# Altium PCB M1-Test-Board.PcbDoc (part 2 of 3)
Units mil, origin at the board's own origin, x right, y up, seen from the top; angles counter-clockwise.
Board outline 3977 x 5000 mil, 4 copper layers (Top, GND Layer 2, Power Layer 3, Bottom), stack 60 mil thick; 191 components, 124 nets, 579 pads, 189 vias.
Unrouted connection lines stored in the file: 80.
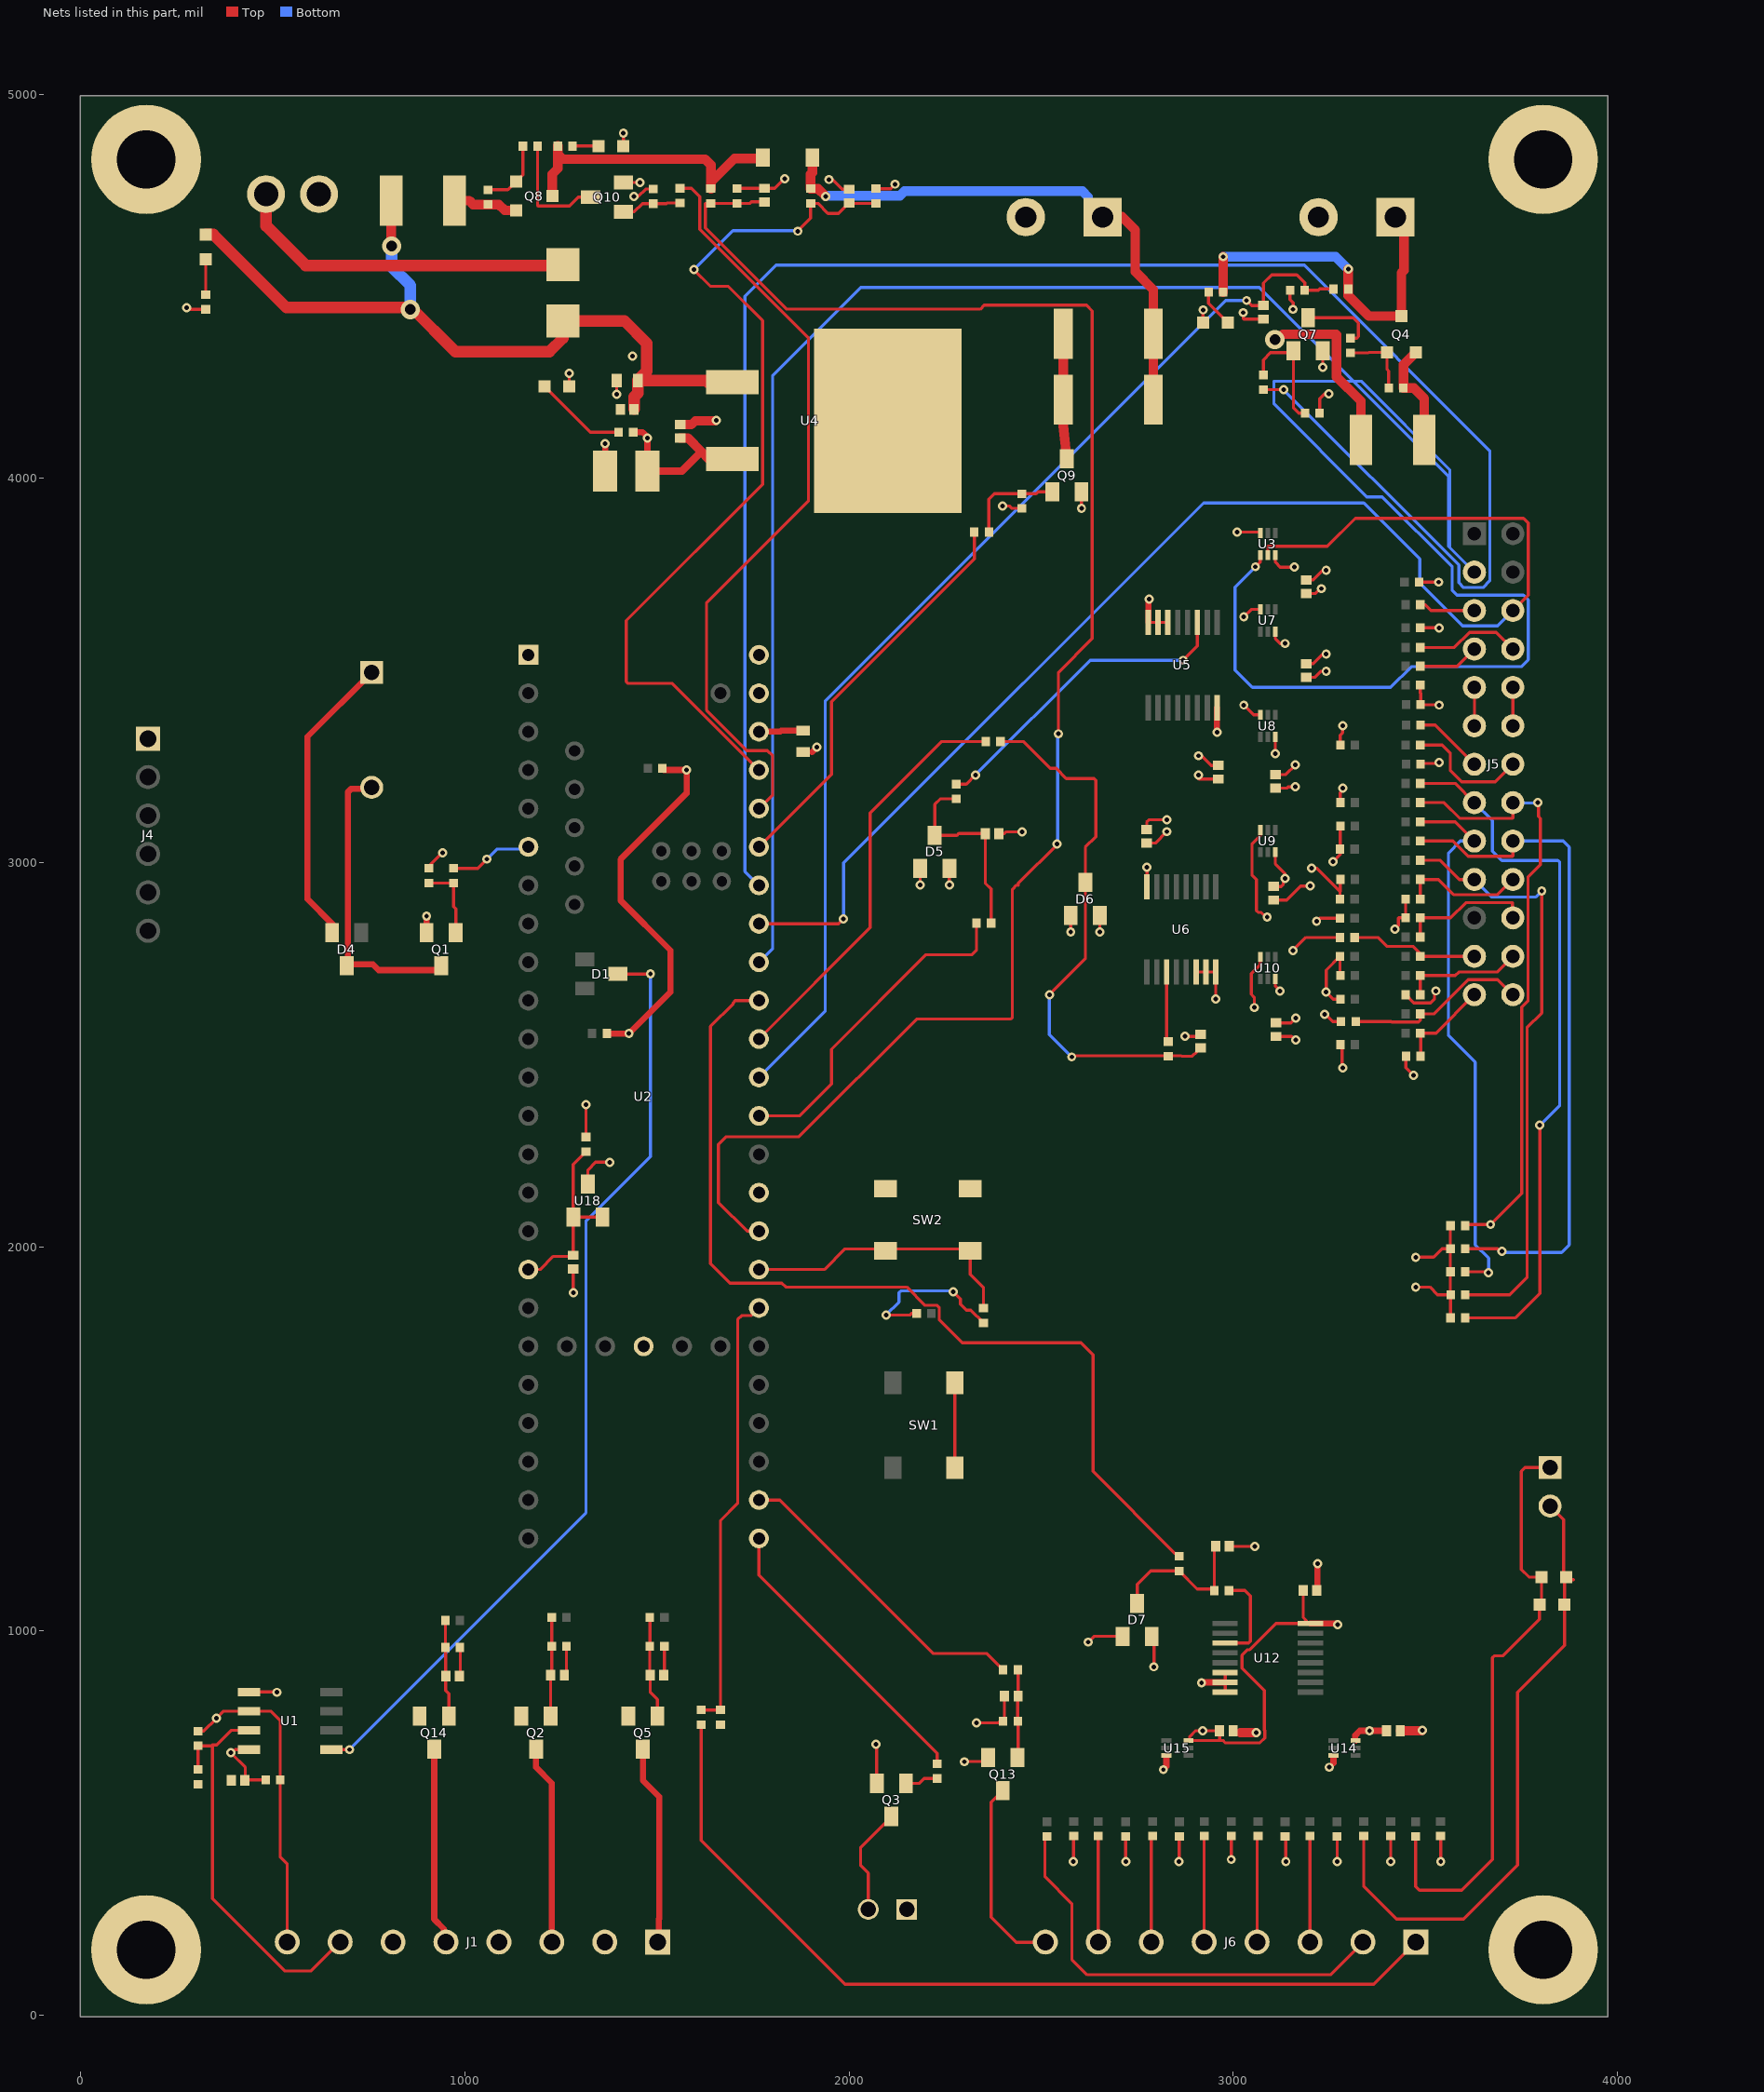
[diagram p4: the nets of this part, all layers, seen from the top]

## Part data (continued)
R2 R3 R8 R22 R23 R24 R25 R26 R27 R28 R29 R30 R31 R32 R33 R34 R35 R36 R37 R38 R39 R40 R41 R42 R43 R44 R45 R46 R47 R48 R49 R52 R60 R61 R62 R63 R64 R65 R66 R67 R70 R73 R88 R90 R92 R94 R99 R100 R102 R103 R104 R108 R117 R118 R119 R120 R121: library part Res-00002, "Thick Film 0402 10K OHM 1% 1/16W 0402", Case Code (Imperial)=0402, Case Code (Metric)=1005, LCSC Part Number=C25744, Manufacturer=Yageo, Manufacturer Part Number=RC0402FR-0710KP, Max Operating Temperature=155°C, Max Power Dissipation=63mW, Min Operating Temperature=-55°C, Power Rating=62.5mW, Resistance=10k, Resistor Type="Thick Film", Supplier Part Number 1=YAG1249CT-ND, Temperature Coefficient=150ppm/°C, Tolerance=1%
R4 R5 R82: library part Res-00009, "Thick Film 0402 330 Ohm 1% 1/16W ±100ppm/°C Molded SMD Paper T/R", Case Code (Imperial)=0402, Case Code (Metric)=1005, LCSC Part Number=C12246, Manufacturer=Yageo, Manufacturer Part Number=AF0402FR-07330RL, Max Operating Temperature=155°C, Max Power Dissipation=63mW, Min Operating Temperature=-55°C, Power Rating=62.5mW, Resistance=330R, Resistor Type="Thick Film", Supplier Part Number 1=13-AF0402FR-07330RLCT-ND, Temperature Coefficient=100ppm/°C, Tolerance=1%
R6 R89 R101 R113: library part Res-00004, "Thick Film 0402 5.1K Ohm 1% 1/16W 0402", Case Code (Imperial)=0402, Case Code (Metric)=1005, LCSC Part Number=C25905, Manufacturer="Stackpole Electronics", Manufacturer Part Number=RMCF0402FT5K10, Max Operating Temperature=155°C, Max Power Dissipation=63mW, Min Operating Temperature=-55°C, Power Rating=62.5mW, Resistance=5.1k, Resistor Type="Thick Film", Supplier Part Number 1=RMCF0402FT5K10CT-ND, Temperature Coefficient=100ppm/°C, Tolerance=1%
R7 R85: library part Res-00001, "Thick Film 0402 1K Ohm 1% 1/8W 0402", Case Code (Imperial)=0402, Case Code (Metric)=1005, LCSC Part Number=C21190, Manufacturer="TE Connectivity", Manufacturer Part Number=CRGP0402F1K0, Max Operating Temperature=155°C, Max Power Dissipation=125mW, Min Operating Temperature=-55°C, Power Rating=0.125W, Resistance=1k, Resistor Type="Thick Film", Supplier Part Number 1=A130355CT-ND, Temperature Coefficient=100ppm/°C, Tolerance=1%
R9 R10 R96 R105 R109 R116 R124 R125: library part Res-00003, "Thick Film 0402 100K OHM 1% 1/16W 0402", Case Code (Imperial)=0402, Case Code (Metric)=1005, LCSC Part Number=C25741, Manufacturer="Stackpole Electronics", Manufacturer Part Number=RMCF0402FT100K, Power Rating=62.5mW, Supplier Part Number 1=RMCF0402FT100KCT-ND
R11 R12 R13 R14 R15 R16 R50 R51 R53 R54 R55 R56 R57 R68 R69 R71 R72: library part Res-00011, "Res Thick Film 0402 51K Ohm 1% 0.063W(1/16W) ±100ppm/C Pad SMD Automotive T/R", Case Code (Imperial)=0402, Case Code (Metric)=1005, LCSC Part Number=C25794, Manufacturer="Stackpole Electronics", Manufacturer Part Number=RMCF0402FT51K0, Max Operating Temperature=155°C, Max Power Dissipation=63mW, Min Operating Temperature=-55°C, Resistance=51kR, Resistor Type="Thick Film", Supplier Part Number 1=RMCF0402FT51K0CT-ND, Temperature Coefficient=100ppm/°C, Tolerance=1%
R17 R21 R58 R59 R93 R106 R107 R111 R112 R114: library part Res-00008, "Thick Film 0402 2.8K Ohm 1% 0.063W ±100ppm/°C Molded SMD Paper T/R", Case Code (Imperial)=0402, Case Code (Metric)=1005, LCSC Part Number=C62741, Manufacturer="Stackpole Electronics", Manufacturer Part Number=RMCF0402FT2K80, Max Operating Temperature=155°C, Max Power Dissipation=63mW, Min Operating Temperature=-55°C, Power Rating=62.5mW, Resistance=2.8kR, Resistor Type="Thick Film", Supplier Part Number 1=RMCF0402FT2K80CT-ND, Temperature Coefficient=100ppm/°C, Tolerance=1%
R18 R19 R20: library part Res-00012, "Res Thick Film 0402 8.2K Ohm 5% 0.063W ±100ppm/°C Molded SMD Paper T/R", Case Code (Imperial)=0402, Case Code (Metric)=1005, LCSC Part Number=C25924, Manufacturer="Stackpole Electronics", Manufacturer Part Number=RMCF0402JT8K20, Max Operating Temperature=155°C, Max Power Dissipation=63mW, Min Operating Temperature=-55°C, Resistance=8.2kR, Resistor Type="Thick Film", Supplier Part Number 1=738-RMCF0402JT8K20CT-ND, Temperature Coefficient=100ppm/°C, Tolerance=5%
R97 R98: library part Res-00005, "Thick Film  220 OHM 5% 1W 2512", Case Code (Imperial)=2512, Case Code (Metric)=6432, LCSC Part Number=C38808, Manufacturer="Stackpole Electronics", Manufacturer Part Number=RMCF2512JT220R, Max Operating Temperature=155°C, Max Power Dissipation=1W, Min Operating Temperature=-55°C, Resistance=220R, Resistor Type="Thick Film", Supplier Part Number 1=RMCF2512JT220RCT-ND, Temperature Coefficient=200ppm/°C, Tolerance=5%
R110: library part Res-00010, "Thick Film 0402 680 Ohm 1% 0.063W(1/16W) ±100ppm/C Pad SMD Automotive T/R", Case Code (Imperial)=0402, Case Code (Metric)=1005, LCSC Part Number=C25130, Manufacturer="Stackpole Electronics", Manufacturer Part Number=RMCF0402FT680R, Max Operating Temperature=155°C, Max Power Dissipation=63mW, Min Operating Temperature=-55°C, Package Quantity=10000, Power Rating=62.5mW, Resistance=680R, Resistor Type="Thick Film", Supplier Part Number 1=RMCF0402FT680RCT-ND, Temperature Coefficient=100ppm/°C, Tolerance=1%
SW1: library part SW-0002, "Switch Tactile N.O. SPST Round Button J-Bend", Case/Package=SMD/SMT, Color=Black, Contact Current Rating=50mA, LCSC Part Number=C221748, Manufacturer="ITT C&K", Max Operating Temperature=85°C, Max Voltage Rating (DC)=32V, Min Operating Temperature=-40°C, Operating Force=5N, Package Quantity=1, Power Rating=1W, Supplier Part Number 1=401-1784-1-ND
SW2: library part SW-0001, "Switch Tactile N.O. SPST Round Button J-Bend", Actuator Color=Blue, Case/Package=SMD/SMT, Current Rating=50mA, LCSC Part Number=C221766, Manufacturer="ITT C&K", Manufacturer Part Number=KSC741JLFS, Max Operating Temperature=85°C, Max Voltage Rating (DC)=32V, Min Operating Temperature=-40°C, Operating Force=4N, Package Quantity=1000, Power Rating=1W, Ratings="IP67,Waterproof,Dust Tight", Supplier Part Number 1=CKN10309CT-ND
U1: library part dd-0001, "IC TXRX RS485 HALF DUPLEX 8SOIC", BOM_JLCPCB Part Class="Basic Part", BOM_Manufacturer=EXAR, BOM_Manufacturer Part=SP485EEN-L/TR, Case/Package=SOIC, LCSC Part Number=C6855, Manufacturer=Exar, Max Operating Temperature=85°C, Max Power Dissipation=550mW, Max Supply Voltage=5.25V, Min Operating Temperature=-40°C, Min Supply Voltage=4.75V, Nominal Supply Current=900uA, Operating Supply Voltage=5V, Package Display=No, Package Quantity=2500
U2: library part Mod-0004, "Teensy 4.1 Development Board", Manufacturer=SparkFun, Manufacturer Part Number=DEV-16771, Supplier Part Number 1=1568-DEV-16771-ND
U3 U7 U8 U9 U10 U14 U15: library part Diode-0012, "TVS DIODE 5.5VWM SOT6", Breakdown Voltage=11V, Capacitance=1.5pF, Case/Package=SOT, Clamping Voltage=105.5V, LCSC Part Number=C527516, Leakage Current=1nA, Manufacturer="Texas Instruments", Max Operating Temperature=85°C, Max Power Dissipation=100W, Min Operating Temperature=-40°C, Operating Supply Voltage=5.5V, Package Quantity=1, Peak Pulse Current=5.5A, Power Line Protection=Yes, Supplier Part Number 1=296-21887-1-ND
U4: library part LDO-0003, "IC REG LDO 5V 1.5A D2PAK", Case/Package=TO-263, Dropout Voltage=2V, LCSC Part Number=C15077, Manufacturer=STMicroelectronics, Max Input Voltage=35V, Max Operating Temperature=125°C, Max Output Current=1.5A, Min Input Voltage=10V, Min Operating Temperature=0°C, Min Output Voltage=4.8V, Nominal Output Voltage=5V, Package Quantity=1000, Power Supply Rejection Ratio (PSRR)=62dB, Quiescent Current=8mA, Supplier Part Number 1=497-1171-2-ND
U5 U6 U12: library part AIC-0001, "5-V, 8: 1, 1-channel analog mutliplexer 16-TS", Case/Package=TSSOP, Dual Supply Voltage=3V, Generic Part Number=CD74HC4051, High Level Output Current=25mA, LCSC Part Number=C352826, Manufacturer="Texas Instruments", Max Dual Supply Voltage=5V, Max Operating Temperature=125°C, Max Supply Voltage=6V, Min Dual Supply Voltage=1V, Min Operating Temperature=-55°C, Min Supply Voltage=2V, Nominal Supply Current=16uA, On-State Resistance=130R, Operating Temperature Range(C)="-55 to 125", Package Quantity=1, Rating=Catalog, Supplier Part Number 1=29AH3620
U18: library part AIC-0002, "V-Ref Adjustable 2.5V to 36V 100mA 3-Pin SOT-", Case/Package=SOT-23-3, Cathode Current=60uA, LCSC Part Number=C3113, Manufacturer="ON Semiconductor", Max Input Voltage=2.525V, Max Operating Temperature=125°C, Max Output Current=100mA, Max Output Voltage=36V, Min Input Voltage=2.475V, Min Operating Temperature=-40°C, Min Output Voltage=2.5V, Package Quantity=3000, PartNumber=TL431ACLP, Rating=Catalog, Supplier Part Number 1=NCP431AVSNT1GOSCT-ND, Temp Coeff(Max)(ppm/ degree C)=92, Temp Coeff(Typ)(ppm/ degree C)=34, Temperature Coefficient=50ppm/°C, Tolerance=1%

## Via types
v1: diameter 24, hole 12, Top to Bottom, 186 vias
v2: diameter 50, hole 28, Top to Bottom, 3 vias

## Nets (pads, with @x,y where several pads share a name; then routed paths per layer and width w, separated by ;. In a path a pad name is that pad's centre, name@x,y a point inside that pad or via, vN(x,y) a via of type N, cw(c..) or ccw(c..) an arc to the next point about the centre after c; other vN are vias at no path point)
+3.3V: D5.2 D6.2 D7.2 F3.2 R2.2 R6.2 R73.2 R117.2 | length 1603.9
  Top w8: F3.2@1880,3287.44 1903.22,3287.44 ; v1(2096.4,1822.31) 2159.03,1822.31 2162.88,1826.16 R2.2@2175.91,1826.16 ; v1(2261,2942) D5.2@2261,2985 ; v1(2271.4,1882.31) 2289.98,1863.73 2289.98,1850.52 2305.5,1835 2316.9,1835 R73.2@2350,1801.9 ; v1(2653,2819) D6.2@2653,2862 ; D7.2@2788,985.77 2793.76,980 v1(2793.76,906.57)
  Top w16: R6.2@1369.09,2555 v1(1427,2555) 1535,2663 1535,2771.38 1405,2901.38 1405,3008.19 1577,3180.19 v1(1577,3241) 1518.09,3241 R117.2@1514.09,3245 ; 1903.22,3287.44 v1(1915.72,3299.94)
  Bottom w8: v1(2096.4,1822.31) 2130,1855.92 2130,1880.31 2134.69,1885 2268.71,1885 v1(2271.4,1882.31)
+5V: BUZ1.1 C1.1 C4.2 C6.2 C8.2 C9.2 C10.2 C11.2 C12.2 C15.2 C18.2 C19.2 C27.1 C28.2 D4.2 R4.2 R11.2 R12.2 R13.1 R40.1 R42.2 R43.2 R44.1 R46.1 R48.1 R68.1 R69.1 R82.1 R110.1 U1.8 U2.VIN U3.6 U4.3 U5.16 U6.16 U7.6 U8.6 U9.6 U10.6 U12.16 U14.6 U15.6 | length 4164
  Top w8: v1(390,682.61) v1@391.95,680.65 ; U1.8@437.75,691 402.3,691 v1@391.95,680.65 ; R4.2@480.9,612.21 428.2,612.21 428.2,644.41 v1@391.95,680.65 ; R82.1@1315,2285.47 v1(1315,2370) ; C6.2@2775,3050.6 2797.29,3050.6 v1(2827.19,3080.5) ; U6.16@2775.43,2937 v1(2775.43,2988) ; U15.6@2883.94,714.68 2963.29,714.69 ; 2886.76,720.79 2886.76,725.36 2901.41,740 C19.2@2964.6,740 2964.6,716 2963.29,714.69 ; v1(2909.38,3278) 2917.93,3278 2943.23,3252.7 C8.2@2961.57,3252.7 ; U10.6@3109.69,2696.85 3109.68,2678.36 v1(3122.18,2665.86) ; U9.6@3109.69,3027.06 3109.68,2996.07 3134.68,2971.07 v1(3134.68,2958.57) 3134.68,2954.24 3130,2949.56 3130,2942.39 3125.31,2937.7 C11.2@3105,2937.7 C11.2@3113,2945.7 ; v1(3109.68,3283.57) U8.6@3109.69,3327.06 ; U7.6@3109.69,3601.06 3109.68,3582.57 3122.18,3570.07 v1(3134.68,3570.07) ; U3.6@3109.69,3800 3109.68,3781.51 3122.18,3769.01 v1(3159.68,3769.01) ; C9.2@3110,3229 3136.89,3229 v1(3162.19,3254.3) ; C12.2@3111,2582.7 3150.39,2582.7 v1(3163.19,2595.5) ; v1(3155.5,2771) 3189.5,2805 R43.2@3278,2805 ; C15.2@3182.3,1105 3182.3,1034.55 3190,1026.85 ; C10.2@3190,3517.7 3208.33,3517.7 3233.63,3543 v1(3242.19,3543) ; C4.2@3190,3735.89 3208.33,3735.89 3233.63,3761.19 v1(3242.19,3761.19) ; U12.16@3201,1019.57 3111.57,1019.57 3043,951 3037.5,951 3023,936.5 3023,903 3081,845 3081,742 3082,741 3082,721 3069.5,708.5 2979.19,708.5 2973,714.69 2963.29,714.69 ; v1@3240,2605 3259,2586 R48.1@3280.83,2586 ; v1@3269.06,1019.57 v1@3276.06,1012.57 ; v1(3421,2827) 3430,2836 3430,2855 3431,2856 R44.1@3448.91,2856 R40.1@3448.91,2904.98 ; R46.1@3448.91,2656 3470.22,2634.69 3513.78,2634.69 3524.09,2645 3524.09,2661.09 v1@3528,2665 ; R42.2@3449.81,2496 3449.81,2465.69 v1(3469.5,2446) ; v1(3475,1895) 3512.05,1895 3532.05,1875 R13.1@3566,1875 ; v1(3475,1972.82) 3521.81,1972.82 3544,1995 R11.2@3565.91,1995 ; R13.1@3565,1875 3565,1930 3565,1986.14 R11.2@3565,1989.09 ; R11.2@3565,1990 3565,1995 R12.2@3565,2055 ; R69.1@3565.91,1815 R13.1@3565.91,1874.91
  Top w16: D4.2@655,2840 590,2905 590,3327.73 BUZ1.1@757.27,3495 ; R110.1@1438,4120 1462.5,4120 1473.02,4109.48 1473.02,4109.14 1475,4107.16 v1(1475,4105) 1475,4019.12 C27.1@1475.12,4019 ; v1(2957.95,3339.5) U5.16@2957.95,3403 ; U12.16@3201,1019.57 v1@3269.06,1019.57 ; U14.6@3318.94,714.68 3317.75,715.88 3317.75,728.1 3329.64,740 3339.64,740 C18.2@3399.6,740
  Top w20: C27.1@1475.12,4019 1565,4019 1615.79,4069.79
  Top w24: C28.2@1560,4104.6 1580.97,4104.6 1615.79,4069.79 U4.3@1635.57,4050
  other v1: 2920.94,740.36 3355,740.36 3272.19,1016 3238.37,2604.54 3528,2666
+12V: C25.1 C26.2 D10.2 DS12.1 F1.1 F2.1 U4.1 | length 2498.8
  Top w25: F2.1@807.5,4723.07 808.23,4722.33 808.23,4605.23 v2(808.97,4604.5) ; v2(3108.5,4361.5) 3115.26,4361.5 3128.76,4375 3268,4375 3269,4374 3269,4264.5 3332.5,4201 F1.1@3332.5,4100
  Top w30: DS12.1@325,4634.96 345.04,4634.96 535,4445 860,4445 975,4330 1220,4330 1255,4365 D10.2@1255,4410 1415,4410 1473.02,4351.98 1473.02,4278.54 1450.51,4256.02 C25.1@1450.51,4255 ; C26.2@1440.26,4180 1440.26,4212 1450.51,4222.25 C25.1@1450.51,4255 ; U4.1@1632.57,4250 1627.57,4255 C25.1@1450.51,4255
  Bottom w30: v2(808.97,4604.5) 808.97,4551.03 857.92,4502.08 v2(857.92,4439.5)
BootTarget: R73.1 SW2.3 SW2.4 U2.40 | length 726
  Top w8: U2.40@1765.2,1940.63 1935.63,1940.63 1989.29,1994.29 SW2.3@2305.5,1994.29 ; SW2.3@2315.5,1989.29 2315.5,1928 2350,1893.5 R73.1@2350,1840.09
BuzzerEn: R7.1 U2.4 | length 218.3
  Top w8: R7.1@970,2984.96 1032.96,2984.96 v1(1057,3009)
  Bottom w8: v1(1057,3009) 1083,3035 1159.57,3035 U2.4@1165.2,3040.63
GND: C1.2 C2.2 C3.2 C4.1 C5.2 C6.1 C7.2 C8.1 C9.1 C10.1 C11.1 C12.1 C14.2 C15.1 C18.1 C19.1 C20.2 C22.2 C23.2 C24.2 C25.2 C26.1 C27.2 C28.1 C30.2 C31.2 D5.1 D6.1 D7.1 DS8.2 DS9.2 DS11.2 J1.2 J1.4 J1.6 J4.1 J9.1 J10.2 J11.2 J12.1 MTG1.1 MTG2.1 MTG3.1 MTG4.1 Q1.2 Q2.2 Q3.2 Q5.2 Q7.2 Q9.2 Q10.2 Q13.2 Q14.2 R5.2 R9.2 R10.2 R14.1 R15.1 R16.1 R17.1 R18.1 R19.1 R20.1 R21.1 R38.2 R39.2 R41.1 R45.1 R47.1 R49.1 R50.1 R51.1 R52.1 R53.1 R54.1 R55.1 R56.1 R57.1 R58.1 R59.1 R71.1 R93.2 R96.2 R105.2 R106.2 R107.2 R109.2 R113.2 R116.2 R124.2 R125.2 SW1.1 SW1.2 SW2.1 SW2.2 U1.5 U2.GND1 U2.GND2 U2.GND3 U2.GND4 U3.3 U4.4 U5.6 U5.7 U5.8 U6.6 U6.7 U6.8 U7.3 U8.3 U9.3 U10.3 U12.6 U12.7 U12.8 U14.3 U15.3 U18.3 | length 5592.7
  Top w8: v1(275,4444) 275,4441 276,4440 R113.2@325,4440 ; U1.5@437.75,841 509.09,841 v1(510,840.09) ; R116.2@905.91,2984.96 905.91,2990.91 v1@940,3025 ; C31.2@987.7,882 R125.2@987.7,957 ; C2.2@1258.7,885 1264.09,890.39 R9.2@1264.09,960 ; DS11.2@1271.57,4240 v1(1271.57,4273.75) ; v1(1282,1880) C20.2@1282,1942.3 ; U18.3@1320,2163 1320,2200 1340,2220 v1(1377,2220) ; v1(1395,4219.28) C25.2@1395,4255 ; DS9.2@1412.48,4865 v1(1412.48,4898.75) ; Q10.2@1413,4770.13 v1(1456,4770.13) ; v1(1440,4734.09) 1451.66,4734.09 1470.76,4753.19 R109.2@1490,4753.19 ; C3.2@1517.7,885 1519.09,886.39 R10.2@1519.09,960 ; R106.2@1708,4754.09 1708,4755 C23.2@1780,4755 1806.89,4755 v1(1832.19,4780.3) ; v1(1947.81,4778) 1956.37,4778 1981.67,4752.7 C24.2@2000,4752.7 ; R107.2@2070,4754.09 2108.59,4754.09 2120,4765.5 v1(2120,4765.91) ; Q3.2@2072,603 v1@2072,703.67 ; v1(2185,2942) D5.1@2185,2985 ; SW1.2@2275,1422.42 SW1.1@2275,1643.42 ; v1@2300,660 2352.07,660 Q13.2@2362,669.93 ; v1(2331.97,760.81) 2388.69,760.81 2392.88,765 R124.2@2400.91,765 2404.6,768.69 C30.2@2404.6,830 ; C5.2@2390,3075 2404,3075 2409,3080 v1(2450,3080) ; v1(2400,3928) 2418.11,3928 2424.3,3921.81 R105.2@2450,3921.81 ; v1(2577,2819) D6.1@2577,2862 ; v1(2584.1,400) 2584.1,465 R52.1@2585,465.91 ; v1(2605,3922) Q9.2@2605,3965 ; v1(2622.91,970.81) 2637.87,985.77 D7.1@2712,985.77 ; R53.1@2720,465 2720,400.91 v1(2720.91,400) ; C6.1@2775,3086 2775,3105.38 2780.92,3111.3 v1(2827.19,3111.3) ; U5.8@2779.87,3626.05 U5.8@2778.82,3625 U5.7@2804.41,3625 U5.6@2830,3625 ; v1@2779.87,3684.95 v1(2780.92,3686) ; v1@2819.09,640 v1@2826.06,646.97 ; v1(2859.1,400) 2859.1,464.1 R54.1@2860,465 ; v1(2874.28,2547.56) C7.2@2910,2547.56 ; U6.6@2903.39,2715 U6.7@2928.98,2715 2949.57,2715 2954.57,2710 v1(2954.57,2645) ; v1(2909.38,3227.5) 2909.38,3218.92 2911,3217.3 C8.1@2961.57,3217.3 ; v1(2917.48,865) v1@2918.5,866.02 ; DS8.2@2921.5,4405 v1(2921.5,4438.75) ; U12.8@2979,840.43 U12.7@2979,866.02 U12.6@2979,891.61 ; v1(2995,405) R55.1@2995,465.91 ; C19.1@3000,740 3014,740 3019,735 ; 3002.56,1220 v1@3060,1220 ; v1(3010,3860) 3068.21,3860 U3.3@3070.31,3857.87 ; v1(3026.31,4431.5) 3026.31,4416 3027.71,4414.6 C22.2@3078.5,4414.6 ; v1(3027.71,3410) 3052.78,3384.94 U8.3@3070.31,3384.94 ; v1(3027.71,3640) 3046.65,3658.94 U7.3@3070.31,3658.94 ; v1(3055,2622.5) 3055,2648.95 3047,2656.95 3047,2710.64 3070.31,2733.95 U10.3@3070.31,2754.73 ; U9.3@3070.31,3084.94 3070.31,3069.5 3048.81,3048 3048.81,2967.3 3060.5,2955.62 3060.5,2874.92 3065.19,2870.23 3073.17,2870.23 3084.91,2858.5 v1(3088.39,2858.5) ; C11.1@3105,2902.3 3139.13,2902.3 3175.83,2939 v1(3200.19,2939) ; C9.1@3110,3193.6 3139.28,3193.6 3142.68,3197 v1(3162.19,3197) ; C12.1@3111,2547.3 3152.19,2547.3 3160.99,2538.5 v1(3163.19,2538.5) ; R56.1@3135,465 3136.97,463.03 v1(3136.97,400) ; R93.2@3148.12,4490 3148.12,4465.15 3156,4457.27 v1(3156,4440) ; C10.1@3190,3482.3 3213.13,3482.3 3228.83,3498 v1(3242.19,3498) ; C4.1@3190,3700.49 3214.73,3700.49 3227.24,3713 v1(3229.69,3713) ; v1(3204.5,2985.47) 3217,2985.47 3278.24,2924.24 ; v1@3214.73,2845 3224.73,2855 R47.1@3278,2855 ; R96.2@3225,4170 3225,4207.5 3237.5,4220 v1(3248.91,4220) ; v1(3233,4289) Q7.2@3233,4332 ; v1(3250,645) 3261.06,656.06 ; v1(3260,3002) 3278.91,3020.91 3278.91,3065.91 ; R57.1@3270,465 3270.91,464.09 v1(3270.91,400) ; R50.1@3278,3034.79 3278,3065 3278.91,3065.91 ; R39.2@3278.91,2526 3283.32,2521.59 3283.32,2466.88 v1(3285,2465.19) ; R41.1@3278.91,2644.19 3260.81,2644.19 v1(3242,2663) 3242,2720 R38.2@3278,2756 3278,2706.91 R45.1@3278.91,2706 ; R14.1@3278.91,2956 3278.91,2924.91 3278.24,2924.24 ; R15.1@3278.91,3095 3278.91,3065.91 ; R51.1@3278.91,3156 3278.91,3181.75 3285,3187.84 v1(3285,3193.5) ; R21.1@3278.91,3306 3278.91,3331.75 3285,3337.84 v1(3285,3356) ; v1(3410,400) R58.1@3410,465.91 ; R19.1@3484.09,3730 v1(3535,3730) ; R18.1@3487.09,3462.02 3487.09,3441 3488,3440.09 R17.1@3488,3411 3488.5,3410.5 3535.5,3410.5 v1(3536,3410) ; R20.1@3487.09,3611 v1@3532,3611 ; R16.1@3488,3256 3490,3258 3534,3258 v1(3536,3260) ; v1@3491.5,740 v1(3492.29,740.79) ; R59.1@3540,465.91 3540.41,465.5 v1(3540.41,400) ; 3278.24,2924.24 3278,2924 R49.1@3278,2904.98 3278.24,2924.24
  Top w16: Q1.2@900,2817.42 v1(900,2860.42) ; C27.2@1365.12,4019 v1(1365.12,4090.15) ; U5.8@2779.87,3626.05 v1@2779.87,3684.95 ; v1@2826.06,646.97 U15.3@2826.06,675.32 ; v1@2918.5,866.02 U12.7@2979,866.02 ; C15.1@3217.7,1105 3218.85,1106.15 3218.85,1173.85 v1(3220,1175) ; 3261.06,656.06 U14.3@3261.06,675.32
  Top w24: C28.1@1560,4140 1589.5,4140 1599.5,4150 v1@1652.36,4150 ; 3019,735 v1(3060,735) ; C18.1@3435,740 v1@3491.5,740
  other v1: 2818.19,638.9 2300,659.5 2070,704.48 3055.87,1220.28 3216.93,2847.07 941.93,3025.03 3536,3610.7 1654.31,4151 1436,4318.19
M1Boot1: R70.1 U2.34 | length 818.8
  Top w8: U2.34@1765.2,1340.63 1819.37,1340.63 2218.73,941.27 2358.25,941.27 R70.1@2400.91,898.61
NetBUZ1_2: BUZ1.2 D4.3 Q1.3 | length 787.5
  Top w16: D4.3@692,2731.42 695.58,2735 760,2735 775,2720 928,2720 938,2730 Q1.3@938,2731.42 ; 695,2757.75 695,2740 695,3182.92 704.37,3192.29 753.78,3192.29 BUZ1.2@757.27,3195.79
NetC2_1: C2.1 Q2.1 R3.2 R9.1 | length 258.2
  Top w8: Q2.1@1223,778 1223,884.7 C2.1@1223.3,885 1225.91,887.61 R9.1@1225.91,960 R3.2@1225.91,1035
NetC3_1: C3.1 Q5.1 R8.2 R10.1 | length 265.7
  Top w8: R8.2@1481.91,1035 1481.91,961 R10.1@1480.91,960 1480.91,886.39 C3.1@1482.3,885 1482.3,840.09 1501,821.39 Q5.1@1501,778
NetC5_1: C5.1 D5.3 R111.1 R118.2 | length 505.1
  Top w8: R111.1@2279,3165.91 2237.5,3165.91 2223,3151.41 D5.3@2223,3071 2281,3071 2285.51,3075.51 C5.1@2345,3075.51 ; C5.1@2354.6,3075 2354.6,2946.56 2369.79,2931.36 R118.2@2369.79,2842.52
NetC7_1: C7.1 D6.3 R112.1 R119.2 | length 1428.3
  Top w8: R119.2@2394.09,3315 2453.5,3315 2523.5,3245 2539.3,3245 2565.5,3218.8 2637.56,3218.8 2642.25,3214.11 2642.25,3167.26 ; v1(2521.5,2655.82) 2615,2749.32 D6.3@2615,2948 2615,3040 2642.25,3067.25 2642.25,3165 ; v1@2577.81,2496.81 2830.73,2496.81 2865,2496.81 2865.81,2496 2893.71,2496 2905,2507.29 2905,2509.3 2912.21,2516.51 C7.1@2914.22,2516.51
  Bottom w8: v1(2521.5,2655.82) 2521.5,2552.07 v1(2579.57,2494)
NetC14_1: C14.1 D7.3 R114.1 R120.2 | length 402.1
  Top w8: D7.3@2750,1071.77 2750,1120.8 2785.11,1155.91 R120.2@2859.1,1155.91 2906,1109 2946.91,1109 R114.1@2950.91,1105 2950.91,1216.31 C14.1@2954.6,1220
NetC20_1: C20.1 R82.2 U2.25 U18.1 U18.2 | length 491.4
  Top w8: U2.25@1165.2,1940.63 1195.63,1940.63 1230,1975 1279.3,1975 C20.1@1282,1977.7 U18.1@1282,2077 ; R82.2@1315,2247.28 1282,2214.28 U18.1@1282,2077 ; U18.2@1358,2077 U18.1@1282,2077
NetC22_1: C22.1 R90.1 R93.1 U2.15 | length 2908.7
  Top w8: v1(3035,4463) 3048,4450 C22.1@3078.5,4450 3078.5,4508.5 3100,4530 3165.5,4530 3186.31,4509.19 R93.1@3186.31,4490 3222,4490 3225,4493 R90.1@3261.26,4493
  Bottom w8: U2.15@1765.2,2440.63 1938,2613.43 1938,3421 2980,4463 v1(3035,4463)
NetC23_1: C23.1 R102.1 R106.1 U2.41 | length 4440.1
  Top w8: U2.41@1765.2,2040.63 1734.37,2040.63 1660,2115 1660,2266.26 1680,2286.26 1869.76,2286.26 2176.05,2592.55 2420.31,2592.55 2425,2597.23 2425,2930.63 2435,2940.63 ; C23.1@1780,4719.6 1745.69,4719.6 1742,4715.91 R106.1@1708,4715.91 R102.1@1640,4715.91 1627,4715.91 1626,4714.91 1626,4652.01 1837.51,4440.5 2341.53,4440.5 2351.91,4450.88 2617.94,4450.88 2633,4435.81 2633,3583 2545,3495 v1(2545,3335) ; 2440,2940.63 2440,2945.6 v1@2545,3050.6
  Bottom w8: v1(2541.41,3048) 2543.2,3049.8 2543.2,3333.2 v1(2545,3335)
NetC24_1: C24.1 R103.1 R107.1 U2.23 | length 2355.7
  Top w8: v1(1596,4543.19) 1639.19,4500 1685,4500 1774.62,4410.38 1774.62,3984.62 1420,3630 1420,3471.06 1424.69,3466.38 1539.45,3466.38 U2.23@1765.2,3240.63 ; v1(1866,4643.54) 1900,4677.54 R103.1@1900,4715.91 1919.09,4715.91 1945,4690 1972.7,4690 C24.1@2000,4717.3 2001.39,4715.91 R107.1@2070,4715.91
  Bottom w8: v1(1596,4543.19) 1697.81,4645 v1@1870,4645
NetC30_1: C30.1 Q13.1 R70.2 R124.1 | length 230.6
  Top w8: Q13.1@2438,669.93 2440,671.93 2440,764.09 R124.1@2439.09,765 2439.09,829.09 C30.1@2440,830 2440,897.71 R70.2@2439.09,898.61
NetC31_1: C31.1 Q14.1 R121.2 R125.1 | length 256.4
  Top w8: R121.2@948.91,1027 948.91,957.61 949.51,957 949.51,882.79 C31.1@950.3,882 949.51,881.21 949.51,844.79 958,836.3 Q14.1@958,775
NetD1_3: D1.3 U1.1 | length 2472.5
  Top w8: U1.1@652.25,691 v1(699,691) ; D1.3@1398,2710 v1@1480,2710
  Bottom w8: v1(699,691) 1315,1307 1315,2066.38 1482.9,2234.29 v1(1482.9,2710)
NetD9_1: D9.1 Q8.3 R101.2 R102.2 | length 771.4
  Top w25: Q8.3@1227.24,4735 1227.24,4792 1241.81,4806.57 1241.81,4843.19 ; R101.2@1241.81,4865 1241.81,4843.19 ; R102.2@1640,4754.09 1640,4771.5 ; D9.1@1775.5,4832 D9.1@1775.5,4835 ; D9.1@1775.5,4833 1701.5,4833 1640,4771.5 ; 1241.81,4843.19 1254,4831 1625,4831 1640,4816 1640,4771.5
NetD9_2: D9.2 J11.1 R97.1 R98.1 R103.2 | length 1403.9
  Top w25: D9.2@1904.5,4835 1904.5,4796.5 1900,4792 R103.2@1900,4754.09 1918.91,4754.09 v1(1939,4734) ; 2710,4681 2745,4646 2745,4538.13 2792.13,4491 R97.1@2792.13,4376.02 R98.1@2792.13,4205
  Bottom w25: v1(1939,4734) 1940.91,4735.91 2132.42,4735.91 2144.52,4748 2607,4748 2622.5,4732.5 2622.5,4717.5 J11.1@2660,4680
NetD10_1: D10.1 J12.2 | length 898.9
  Top w30: J12.2@482.21,4740 482.21,4657.25 585.2,4554.25 1253.25,4554.25 D10.1@1255,4556
NetDS5_1: DS5.1 DS6.2 J8.2 R61.2 | length 1640.6
  Top w8: R61.2@3340,465.91 3340,335 3425,250 3600,250 3740,390 3740,839.64 3862.48,962.12 DS6.2@3862.48,1067.95 3862.48,1127.95 3867.48,1132.95 3885.67,1132.95 ; J8.2@3825,1325 3860,1290 3860,1147.48 DS5.1@3867.48,1140
NetDS5_2: DS5.2 DS6.1 J8.1 R60.2 | length 1545.7
  Top w8: R60.2@3475,465 3475,335 3485,325 3595,325 3675,405 3675,930.31 3679.69,935 3702.05,935 3797.52,1030.47 DS6.1@3797.52,1064.61 ; DS6.1@3802.52,1072.95 DS5.2@3802.52,1132.95 ; DS5.2@3802.52,1140 3770,1140 3750,1160 3750,1415 3760,1425 J8.1@3825,1425
NetDS8_1: DS8.1 R89.1 | length 100.9
  Top w8: R89.1@2935.91,4485 2935.91,4455.55 DS8.1@2986.46,4405
NetDS9_1: DS9.1 R101.1 | length 67.5
  Top w8: R101.1@1280,4865 DS9.1@1347.52,4865
NetDS11_1: DS11.1 R110.2 | length 242.9
  Top w8: DS11.1@1206.61,4240 1326.61,4120 R110.2@1399.81,4120
NetDS12_2: DS12.2 R113.1 | length 91.8
  Top w8: R113.1@325,4478.19 DS12.2@325,4570
NetF1_2: F1.2 Q4.2 R88.1 | length 279.3
  Top w25: Q4.2@3475.28,4327.76 3443.19,4295.66 R88.1@3443.19,4235 3470,4235 3497.5,4207.5 F1.2@3497.5,4100
NetF2_2: F2.2 Q8.2 R100.1 | length 170.8
  Top w25: F2.2@972.5,4723.07 1011,4723.07 1021.03,4713.03 R100.1@1060,4713.03 1088,4713.03 1103.43,4697.6 Q8.2@1132.76,4697.6
NetF3_1: F3.1 U2.3.3V_2 | length 115.8
  Top w8: 1821,3340.63 1823.32,3342.95
  Top w16: U2.3.3V_2@1765.2,3340.63 1821,3340.63 ; 1823.32,3342.95 F3.1@1880,3342.95
NetJ1_1: J1.1 Q5.3 | length 521.3
  Top w16: Q5.3@1463,692 1463,610.93 1505.7,568.23 1505.7,250.7 1505,250 1505,193.23 J1.1@1501.77,190
NetJ1_3: J1.3 Q2.3 | length 519.1
  Top w16: Q2.3@1185,692 1185,645 1226.18,603.82 J1.3@1226.18,190
NetJ1_5: J1.5 Q14.3 | length 511.7
  Top w16: Q14.3@920,689 920,249.5 945.02,224.48 945.02,195.57 J1.5@950.59,190
NetJ1_7: J1.7 R1.1 R5.1 U1.7 | length 1060.1
  Top w8: R5.1@305,640 R1.1@305,701 ; U1.7@437.75,741 391,741 353.3,703.3 342.3,703.3 ; J1.7@675,190 600,115 530,115 342.3,302.7 342.3,703.3 ; R1.1@305,701 340,701 342.3,703.3 ; R1.1@305,701 302.74,701 305,703.26 R1.1@305,701
NetJ1_8: J1.8 R1.2 R4.1 U1.6 | length 831.6
  Top w8: R1.2@302.74,739.19 319.58,739.19 v1(353,772.61) 371.39,791 U1.6@437.75,791 494,791 519.09,765.91 R4.1@519.09,612.21 519.09,410.91 537.2,392.8 J1.8@537.2,190
NetJ5_3: J5.3 U2.18 U3.4 | length 6893.4
  Top w8: v1(3058,3770) 3070.31,3782.31 U3.4@3070.31,3800
  Bottom w8: U2.18@1765.2,2740.63 1801,2776.43 1801,4268 2030,4497 3068,4497 3312,4253 ; v1(3058,3770) 3005,3717 3005,3501 3050,3456 3410,3456 3464,3510 3750,3510 3768,3528 3768,3683.5 3755.5,3696 3582.75,3696 3570.25,3708.5 3570.25,3769.66 3387.91,3952 3348,3952 3106,4194 3106,4252 3107,4253 3312,4253 ; J5.3@3628,3756 3564,3820 ; 3312,4253 3333,4253 3564,4022 3564,4004.45 3564,3823.45 3564,3820 ; 3312,4253 3560.55,4004.45 3560.55,3823.45 3564,3820
NetJ5_5: J5.5 R22.2 | length 147.1
  Top w8: R22.2@3487.09,3671 3500.12,3671 3515.12,3656 J5.5@3628,3656
NetJ5_6: J5.6 U2.19 U3.5 | length 3667.1
  Top w8: U2.19@1765.2,2840.63 1972.13,2840.63 v1(1985,2853.5) ; U3.5@3090,3800 3090,3822 3091,3823 3245,3823 3318,3896 3755.5,3896 3768,3883.5 3768,3696 J5.6@3728,3656
  Bottom w8: v1(1985,2853.5) 1986,2854.5 1986,2999 2923,3936 3340,3936 3486,3790 3486,3727 3597,3616 3688,3616 J5.6@3728,3656
NetJ5_7: J5.7 R23.2 | length 159.5
  Top w8: R23.2@3487.09,3511 3583,3511 J5.7@3628,3556
NetJ5_8: J5.8 R24.1 | length 275.1
  Top w8: R24.1@3487.09,3559.79 3575.92,3559.79 3615.33,3599.19 3684.81,3599.19 J5.8@3728,3556
NetJ5_9: J5.9 J5.11 | length 100
  Top w8: J5.11@3628,3356 J5.9@3628,3456
NetJ5_10: J5.10 J5.12 | length 100
  Top w8: J5.12@3728,3356 J5.10@3728,3456
NetJ5_13: J5.13 R25.2 | length 182.2
  Top w8: R25.2@3488,3357.95 3526.05,3357.95 J5.13@3628,3256
NetJ5_14: J5.14 R26.1 | length 326.1
  Top w8: R26.1@3487.09,3306 3544,3306 3565,3285 3565,3240 3595,3210 3682,3210 J5.14@3728,3256
NetJ5_15: J5.15 R27.2 R69.2 | length 1857.3
  Top w8: R27.2@3487.09,3206 3578,3206 J5.15@3628,3156 ; R69.2@3605.23,1815 3735,1815 3798.28,1878.28 v1(3798.28,2316.1)
  Bottom w8: J5.15@3628,3156 3675,3109 3675,3029.64 3699.64,3005 3845.31,3005 3850,3000.31 3850,2367.82 v1(3798.28,2316.1)
NetJ5_16: J5.16 R12.1 R28.1 | length 1585.5
  Top w8: R28.1@3487.09,3156 3548.5,3156 3589.5,3115 3727,3115 3728,3116 J5.16@3728,3156 ; R12.1@3603.19,2055 3606,2057.82 v1(3670,2057.82) 3751.5,2139.32 3751.5,2623.64 3767.5,2639.64 3767.5,2961.57 3800,2994.07 3800,3115 3795,3120 v1@3795,3155
  Bottom w8: J5.16@3728,3156 3729,3155 3792.19,3155 v1(3793.28,3156.1)
NetJ5_17: J5.17 R29.2 R68.2 | length 1442.8
  Top w8: R29.2@3487.09,3106 3578,3106 J5.17@3628,3056 ; R68.2@3605.5,1935 3662.81,1935 v1(3665,1932.82)
  Bottom w8: J5.17@3628,3056 3591.55,3056 3560.55,3025 3560.55,2549.72 3630,2480.28 3630,2005 3665,1970 v1@3665,1927.82
NetJ5_18: J5.18 R11.1 R30.1 | length 1779
  Top w8: R30.1@3487.09,3056 3572.14,3056 3611.64,3016.5 3727,3016.5 3728,3017.5 J5.18@3728,3056 ; R11.1@3604.09,1995 3688.49,1995 3695.67,1987.82 v1(3700,1987.82)
  Bottom w8: v1@3690,1990 3695,1985 3855,1985 3875,2005 3875,3040 3859,3056 J5.18@3728,3056
NetJ5_19: J5.19 R13.2 R31.2 | length 1564
  Top w8: R31.2@3487.09,3005.88 3539.12,3005.88 3589,2956 J5.19@3628,2956 ; R13.2@3604.19,1875 3720,1875 3765,1920 3765,2570 3803.28,2608.28 v1(3803.28,2926.1)
  Bottom w8: J5.19@3628,2956 3674,2910 3787.19,2910 v1(3803.28,2926.1)
NetJ5_20: J5.20 R32.1 R40.2 | length 324.7
  Top w8: R40.2@3487.09,2904.98 R32.1@3487.09,2956 3534,2956 3573.5,2916.5 3688.5,2916.5 J5.20@3728,2956
NetJ5_22: J5.22 R33.1 R44.2 | length 345.8
  Top w8: R33.1@3487.09,2806 R44.2@3487.09,2856 3566,2856 3605.5,2895.5 3727,2895.5 J5.22@3728,2856
NetJ5_23: J5.23 R34.2 R43.1 | length 336
  Top w8: R43.1@3316.19,2805 3376.69,2805 3399.69,2782 3467.7,2782 3487.09,2762.61 R34.2@3487.09,2756 J5.23@3628,2756
NetJ5_24: J5.24 R35.1 R46.2 | length 311.6
  Top w8: R46.2@3487.09,2656 R35.1@3487.09,2706 3578.5,2706 3587.5,2715 3687,2715 J5.24@3728,2756
NetJ5_25: J5.25 R36.2 R42.1 | length 242.7
  Top w8: R42.1@3488,2496 3488,2555.09 R36.2@3487.09,2556 3528,2556 J5.25@3628,2656
NetJ5_26: J5.26 R37.1 R48.2 | length 481.5
  Top w8: R48.2@3319.02,2586 3411.35,2586 3412.66,2584.69 3482.41,2584.69 3487.09,2589.38 R37.1@3487.09,2606 3522.14,2606 3611.64,2695.5 3688.5,2695.5 J5.26@3728,2656
NetJ6_1: J6.1 R72.2 | length 2362.7
  Top w8: R72.2@1615,755.91 1615,454.54 1989.54,80 3365.59,80 J6.1@3475.59,190
NetJ6_2: J6.2 R67.2 | length 1167.5
  Top w8: R67.2@2515,465 2510,460 2510,360 2580,290 2580,145 2620,105 3253.21,105 J6.2@3337.8,189.59 ; J6.2@3335,192.38 J6.2@3337.8,189.59 ; J6.2@3340,191.79 J6.2@3337.8,189.59
NetJ6_3: J6.3 R62.2 | length 276.3
  Top w8: J6.3@3200,189.59 R62.2@3200,465.91
NetJ6_4: J6.4 R63.2 | length 277.5
  Top w8: J6.4@3062.2,189.59 3062.2,463.11 R63.2@3065,465.91
NetJ6_5: J6.5 R64.2 | length 276.6
  Top w8: J6.5@2924.41,189.59 2924.41,465.32 R64.2@2925,465.91
NetJ6_6: J6.6 R65.2 | length 277.7
  Top w8: J6.6@2786.61,189.59 2786.61,462.52 R65.2@2790,465.91
NetJ6_7: J6.7 R66.2 | length 276.3
  Top w8: J6.7@2648.82,189.59 R66.2@2648.82,465.91
NetJ6_8: J6.8 Q13.3 | length 515.1
  Top w8: Q13.3@2400,583.93 2370,553.93 2370,255 2435.41,189.59 2511.02,189.59 J6.8@2515,193.56
NetJ9_2: J9.2 Q3.3 | length 283.4
  Top w8: J9.2@2050,275 2050,369.27 2030,389.27 2030,437 Q3.3@2110,517
NetJ10_1: J10.1 Q4.3 R89.2 R90.2 | length 895.7
  Top w25: R89.2@2974.09,4485 v1(2974.09,4577) ; v1(3299.45,4544.55) R90.2@3299.45,4493 3299.45,4476.05 3353.26,4422.24 Q4.3@3437.88,4422.24 3437.88,4535 3445,4542.12 J10.1@3445,4655
  Bottom w25: v1(2974.09,4577) 3267,4577 v1(3299.45,4544.55)
NetQ1_1: Q1.1 R7.2 R116.1 | length 195.9
  Top w8: R116.1@905.91,2946.77 R7.2@970,2946.77 970,2885 976,2879 Q1.1@976,2817.42
NetQ3_1: Q3.1 R85.2 | length 86.4
  Top w8: Q3.1@2148,603 2182,603 2194.91,615.91 R85.2@2229.03,615.91
NetQ4_1: Q4.1 R88.2 R92.1 | length 190.5
  Top w8: R92.1@3305,4326.81 3352,4326.81 3352.94,4327.76 Q4.1@3400.48,4327.76 3400.48,4283.52 3405,4279 R88.2@3405,4235
NetQ7_1: Q7.1 R94.2 R96.1 | length 309.5
  Top w8: R94.2@3078.5,4269.09 3078.5,4308.5 3097,4327 Q7.1@3157,4327 ; Q7.1@3157,4332 Q7.1@3157,4327 ; R96.1@3186.81,4170 3170.5,4170 3157,4183.5 Q7.1@3157,4327
NetQ7_3: Q7.3 R92.2 | length 194.7
  Top w8: Q7.3@3195,4418 3312.5,4418 3326,4404.5 3326,4369.16 3321.84,4365 R92.2@3305,4365
NetQ8_1: Q8.1 R100.2 R104.1 | length 181.6
  Top w8: R100.2@1060,4751.22 1111.57,4751.22 Q8.1@1132.76,4772.4 1150.91,4790.55 R104.1@1150.91,4865
NetQ9_1: Q9.1 R99.2 R105.1 | length 258.8
  Top w8: R99.2@2364.09,3860 2364.09,3946 2378.09,3960 R105.1@2450,3960 2487,3960 2492,3965 Q9.1@2529,3965
NetQ9_3: Q9.3 R97.2 R98.2 | length 325.5
  Top w25: R97.2@2557.87,4376.02 R98.2@2557.87,4205 2557.87,4137.13 Q9.3@2567,4051
NetQ10_1: Q10.1 R108.2 R109.1 | length 156.4
  Top w8: Q10.1@1413,4694.13 1441,4694.13 1461.87,4715 R109.1@1490,4715 1524,4715 1525.81,4716.81 R108.2@1560,4716.81
NetQ10_3: Q10.3 R104.2 | length 302.9
  Top w8: R104.2@1189.09,4865 1189.09,4710 1190.09,4709 1272,4709 1295.13,4732.13 Q10.3@1327,4732.13
NetR71_2: R71.2 R72.1 U2.39 | length 1151.5
  Top w8: R72.1@1615,794.09 1663.39,794.09 1665.2,795.91 1665.2,1287.06 1710,1331.87 1710,1810 1720.99,1820.99 1745.56,1820.99 U2.39@1765.2,1840.63
NetR85_1: R85.1 U2.33 | length 778.7
  Top w8: U2.33@1765.2,1240.63 1765.2,1144.8 2229.03,680.97 R85.1@2229.03,654.1
NetR94_1: R94.1 U2.20 | length 4896.4
  Top w8: R94.1@3078.5,4230.91 v1(3130.95,4230.91)
  Bottom w8: U2.20@1765.2,2940.63 1729,2976.83 1729,4474 1810,4555 3185,4555 3668,4072 3668,3733.5 3650.5,3716 3600,3716 3587.5,3728.5 3587.5,3774.36 v1(3130.95,4230.91)
NetR99_1: R99.1 U2.21 | length 1051.6
  Top w8: U2.21@1765.2,3040.63 1954,3229.43 1954,3418.5 2325.91,3790.41 R99.1@2325.91,3860
NetR108_1: R108.1 U2.22 | length 1997.6
  Top w8: R108.1@1560,4755 1589.5,4755 1611,4733.5 1611,4647.92 1894.47,4364.45 1894.47,3942.19 1629,3676.72 1629,3395.92 1733.92,3291 1787.5,3291 1801,3277.5 1801,3176.43 U2.22@1765.2,3140.63
NetR111_2: R111.2 U5.3 | length 837.8
  Top w8: R111.2@2279,3204.09 2305.09,3204.09 v1(2329,3228) ; v1(2869.27,3526.5) 2906.77,3564 U5.3@2906.77,3625
  Bottom w8: v1(2329,3228) 2627.5,3526.5 v1(2869.27,3526.5)
NetR112_2: R112.2 U6.3 | length 180
  Top w8: R112.2@2826.61,2535 U6.3@2826.61,2715
NetR114_2: R114.2 U12.3 | length 247.4
  Top w8: U12.3@2979,968.39 3040.31,968.39 3045,973.07 3045,1090.75 3030.75,1105 R114.2@2989.09,1105
NetR118_1: R118.1 U2.14 | length 868.6
  Top w8: U2.14@1765.2,2340.63 1870.63,2340.63 1954,2424 1954,2514 2200,2760 2320,2760 2331.6,2771.6 R118.1@2331.6,2842.52
NetR119_1: R119.1 U2.16 | length 1086.4
  Top w8: U2.16@1765.2,2540.63 2055,2830.43 2055,3129 2241,3315 R119.1@2355.91,3315
NetR120_1: R120.1 U2.17 | length 2504.5
  Top w8: U2.17@1765.2,2640.63 1703.66,2640.63 1698.03,2635 1698.03,2632.03 1639.45,2573.45 1639.45,1956.05 1690.12,1905.38 1824.93,1905.38 1835.31,1895 2150,1895 2197.53,1847.47 2229.05,1847.47 2234.62,1841.91 2234.62,1810.38 2295,1750 2603.95,1750 2635,1718.95 2635,1415 2848.88,1201.12 2852.07,1201.12 R120.1@2859.1,1194.09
